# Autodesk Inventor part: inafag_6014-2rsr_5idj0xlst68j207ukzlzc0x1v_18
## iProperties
Shininess: 64.0
Angle Display Precision: 2
Document Length Units: 11269
Document Angle Units: 11279
Document Time Units: 11290
Document Mass Units: 11283
Document Length Units Precision: 3
Document Angle Units Precision: 2
Compacted: True
Created: 2008-08
Part Number: inafag_6014-2rsr_5idj0xlst68j207ukzlzc0x1v_18
Document SubType Name: Modeling
Designer: tpomodeler
Density: 0.0
Volumn: 0.0
Area: 0.0
PropertySet Name: Model Information
Control State: 0
Master: False
Checked Out: False
Author: tpomodeler
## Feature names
1. inafag_6014-2rsr_5idj0xlst68j207ukzlzc0x1v
